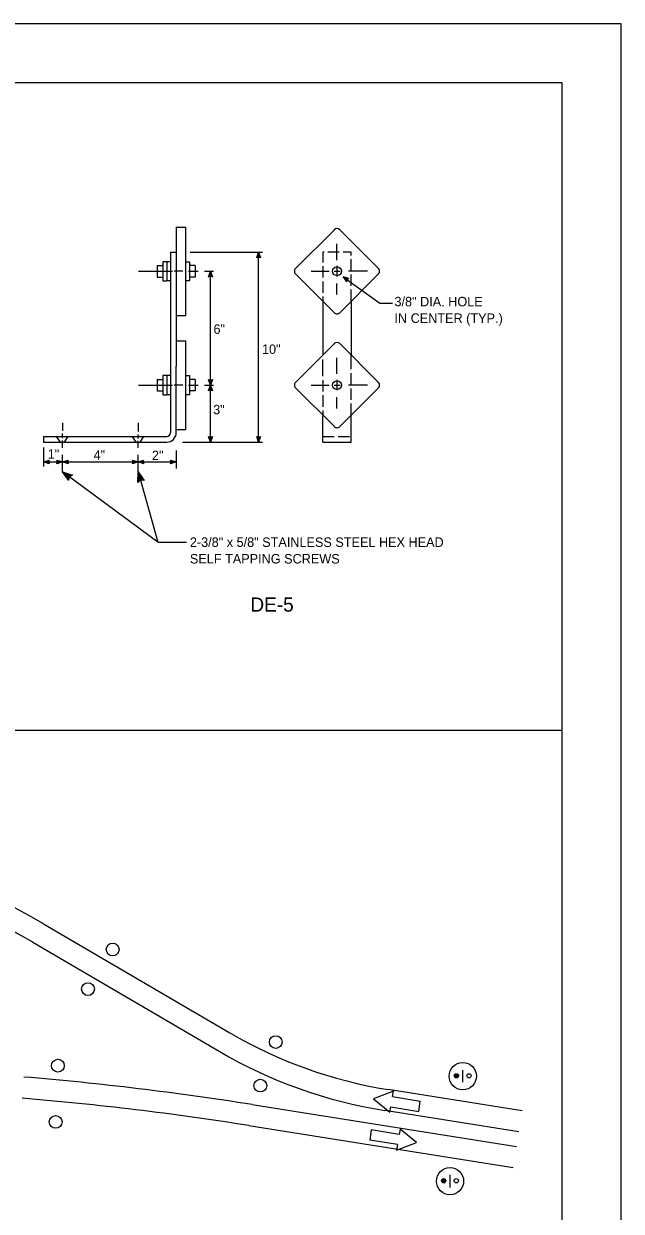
# Model space of a CAD drawing. Extents: x -0.14 to 2.7, y -0.05 to 1.78.
# Drawn here: x 2.172 to 2.698, y 0.736 to 1.781 of the extents above; entities that cross this region are included whole.
import ezdxf

# ---------------------------------------------------------------- set-up
doc = ezdxf.new("R2010")
doc.units = 0
for name, color, linetype in [('BDR_Outer_Perimeter', 7, 'Continuous'), ('BDR_Perimeter', 7, 'Continuous'), ('CT_CSHT_GeneralLabel', 7, 'Continuous')]:
    doc.layers.add(name, color=color, linetype=linetype)

msp = doc.modelspace()

# ---------------------------------------------------------------- linework, layer by layer
at = {"layer": 'BDR_Outer_Perimeter'}
msp.add_lwpolyline([(-0.1354, -0.0521), (2.6979, -0.0521), (2.6979, 1.7812), (-0.1354, 1.7812)], close=True, dxfattribs=at)
at = {"layer": 'BDR_Perimeter'}
for p, q in [((2.6458, 1.7292), (0, 1.7292)), ((2.6458, 0), (2.6458, 1.7292))]:
    msp.add_line(p, q, dxfattribs=at)
at = {"layer": 'CT_CSHT_GeneralLabel'}
for p, q in [((2.3061, 1.6023), (2.3145, 1.6023)), ((2.3061, 1.6023), (2.3061, 1.5801)), ((2.3145, 1.5634), (2.3145, 1.6023)), ((2.4454, 1.5999), (2.4112, 1.5658)), ((2.4843, 1.5658), (2.4501, 1.5999)), ((2.3011, 1.5801), (2.3011, 1.4213)), ((2.3011, 1.5801), (2.3061, 1.5801)), ((2.3061, 1.5801), (2.3061, 1.4798)), ((2.3185, 1.5801), (2.382, 1.5801)), ((2.377, 1.5751), (2.3787, 1.5801)), ((2.3787, 1.5801), (2.3776, 1.5754)), ((2.3787, 1.5801), (2.378, 1.5755)), ((2.3787, 1.5801), (2.3784, 1.5756)), ((2.3787, 1.413), (2.3787, 1.5801)), ((2.3787, 1.5801), (2.3804, 1.5751)), ((2.3787, 1.5801), (2.3787, 1.5756)), ((2.3787, 1.5801), (2.3796, 1.5755)), ((2.3787, 1.5801), (2.3791, 1.5756)), ((2.3787, 1.5801), (2.3799, 1.5753)), ((2.4477, 1.5732), (2.4477, 1.5874)), ((2.2894, 1.5684), (2.2944, 1.5684)), ((2.2894, 1.5684), (2.2894, 1.5583)), ((2.2944, 1.5717), (2.2944, 1.555)), ((2.2978, 1.5717), (2.2944, 1.5717)), ((2.2978, 1.5717), (2.2978, 1.555)), ((2.2978, 1.5717), (2.2978, 1.555)), ((2.3011, 1.5717), (2.2978, 1.5717)), ((2.3145, 1.5717), (2.3178, 1.5717)), ((2.3178, 1.5717), (2.3178, 1.555)), ((2.3229, 1.5684), (2.3178, 1.5684)), ((2.3229, 1.5684), (2.3229, 1.5583)), ((2.4477, 1.5682), (2.4477, 1.5588)), ((2.2729, 1.5634), (2.2965, 1.5634)), ((2.2894, 1.5583), (2.2944, 1.5583)), ((2.2952, 1.5634), (2.303, 1.5634)), ((2.3121, 1.5634), (2.3043, 1.5634)), ((2.3145, 1.5245), (2.3145, 1.5634)), ((2.3171, 1.5634), (2.3254, 1.5634)), ((2.3229, 1.5583), (2.3178, 1.5583)), ((2.3311, 1.5634), (2.3389, 1.5634)), ((2.3346, 1.5583), (2.3363, 1.5634)), ((2.3363, 1.5634), (2.3352, 1.5587)), ((2.3363, 1.5634), (2.3356, 1.5588)), ((2.3363, 1.5634), (2.336, 1.5589)), ((2.3363, 1.5634), (2.338, 1.5583)), ((2.3363, 1.5634), (2.3363, 1.5589)), ((2.3363, 1.5634), (2.3371, 1.5588)), ((2.3363, 1.5634), (2.3367, 1.5589)), ((2.3363, 1.5634), (2.3375, 1.5586)), ((2.3363, 1.4631), (2.3363, 1.5634)), ((2.4112, 1.561), (2.4454, 1.5269)), ((2.425, 1.5634), (2.4407, 1.5634)), ((2.4451, 1.5634), (2.4505, 1.5634)), ((2.4501, 1.5269), (2.4843, 1.561)), ((2.4582, 1.5569), (2.4531, 1.5585)), ((2.4531, 1.5585), (2.4562, 1.5542)), ((2.4531, 1.5585), (2.4567, 1.5559)), ((2.4531, 1.5585), (2.4572, 1.5564)), ((2.4531, 1.5585), (2.4563, 1.5551)), ((2.4531, 1.5585), (2.4576, 1.5567)), ((2.4531, 1.5585), (2.4569, 1.5561)), ((2.4531, 1.5585), (2.4565, 1.5555)), ((2.4531, 1.5585), (2.4562, 1.5547)), ((2.4747, 1.5634), (2.4579, 1.5634)), ((2.2944, 1.555), (2.2978, 1.555)), ((2.3011, 1.555), (2.2978, 1.555)), ((2.3178, 1.555), (2.3145, 1.555)), ((2.4477, 1.5428), (2.4477, 1.5527)), ((2.4352, 1.5371), (2.4352, 1.4898)), ((2.4603, 1.5371), (2.4603, 1.4896)), ((2.3061, 1.5245), (2.3145, 1.5245)), ((2.3061, 1.502), (2.3145, 1.502)), ((2.3145, 1.4631), (2.3145, 1.502)), ((2.4454, 1.4997), (2.4112, 1.4655)), ((2.4843, 1.4655), (2.4501, 1.4997)), ((2.4477, 1.473), (2.4477, 1.4871)), ((2.3061, 1.4213), (2.3061, 1.4798)), ((2.2894, 1.4681), (2.2944, 1.4681)), ((2.2894, 1.4681), (2.2894, 1.4581)), ((2.2944, 1.4715), (2.2944, 1.4547)), ((2.2978, 1.4715), (2.2944, 1.4715)), ((2.2978, 1.4715), (2.2978, 1.4547)), ((2.2978, 1.4715), (2.2978, 1.4547)), ((2.3011, 1.4715), (2.2978, 1.4715)), ((2.3145, 1.4715), (2.3178, 1.4715)), ((2.3178, 1.4715), (2.3178, 1.4547)), ((2.3229, 1.4681), (2.3178, 1.4681)), ((2.3229, 1.4681), (2.3229, 1.4581)), ((2.3363, 1.4631), (2.3346, 1.4681)), ((2.3363, 1.4631), (2.3351, 1.4678)), ((2.3363, 1.4631), (2.3354, 1.4677)), ((2.3363, 1.4631), (2.3359, 1.4676)), ((2.338, 1.4681), (2.3363, 1.4631)), ((2.3363, 1.4631), (2.3374, 1.4678)), ((2.3363, 1.4631), (2.3363, 1.4676)), ((2.3363, 1.4631), (2.337, 1.4676)), ((2.3363, 1.4631), (2.3366, 1.4676)), ((2.4477, 1.4679), (2.4477, 1.4586)), ((2.2729, 1.4631), (2.2965, 1.4631)), ((2.2894, 1.4581), (2.2944, 1.4581)), ((2.2944, 1.4547), (2.2978, 1.4547)), ((2.2952, 1.4631), (2.303, 1.4631)), ((2.3011, 1.4547), (2.2978, 1.4547)), ((2.3121, 1.4631), (2.3043, 1.4631)), ((2.3145, 1.4242), (2.3145, 1.4631)), ((2.3178, 1.4547), (2.3145, 1.4547)), ((2.3171, 1.4631), (2.3254, 1.4631)), ((2.3229, 1.4581), (2.3178, 1.4581)), ((2.3311, 1.4631), (2.3389, 1.4631)), ((2.3346, 1.4581), (2.3363, 1.4631)), ((2.3363, 1.4631), (2.3352, 1.4584)), ((2.3363, 1.4631), (2.3356, 1.4586)), ((2.3363, 1.4631), (2.336, 1.4586)), ((2.3363, 1.413), (2.3363, 1.4631)), ((2.3363, 1.4631), (2.338, 1.4581)), ((2.3363, 1.4631), (2.3363, 1.4586)), ((2.3363, 1.4631), (2.3371, 1.4585)), ((2.3363, 1.4631), (2.3367, 1.4586)), ((2.3363, 1.4631), (2.3375, 1.4584)), ((2.4112, 1.4608), (2.4454, 1.4266)), ((2.425, 1.4631), (2.4407, 1.4631)), ((2.4451, 1.4631), (2.4505, 1.4631)), ((2.4501, 1.4266), (2.4843, 1.4608)), ((2.4747, 1.4631), (2.4579, 1.4631)), ((2.4477, 1.4426), (2.4477, 1.4524)), ((2.4352, 1.413), (2.4352, 1.4362)), ((2.4603, 1.413), (2.4603, 1.4362)), ((2.206, 1.43), (2.206, 1.4229)), ((2.2727, 1.43), (2.2727, 1.4222)), ((2.3061, 1.4242), (2.3145, 1.4242)), ((2.1893, 1.418), (2.1893, 1.413)), ((2.1893, 1.418), (2.2978, 1.418)), ((2.1893, 1.413), (2.2978, 1.413)), ((2.2043, 1.4129), (2.2009, 1.4179)), ((2.206, 1.4163), (2.206, 1.4204)), ((2.206, 1.4078), (2.206, 1.4143)), ((2.2078, 1.4129), (2.2111, 1.4179)), ((2.2709, 1.4129), (2.2676, 1.4179)), ((2.2727, 1.416), (2.2727, 1.4198)), ((2.2727, 1.4078), (2.2727, 1.4142)), ((2.2745, 1.4129), (2.2778, 1.4179)), ((2.3116, 1.413), (2.382, 1.413)), ((2.3363, 1.413), (2.3346, 1.418)), ((2.3363, 1.413), (2.3351, 1.4177)), ((2.3363, 1.413), (2.3354, 1.4176)), ((2.3363, 1.413), (2.3359, 1.4174)), ((2.338, 1.418), (2.3363, 1.413)), ((2.3363, 1.413), (2.3374, 1.4176)), ((2.3363, 1.413), (2.337, 1.4175)), ((2.3363, 1.413), (2.3363, 1.4174)), ((2.3363, 1.413), (2.3366, 1.4174)), ((2.3787, 1.413), (2.3771, 1.418)), ((2.3787, 1.413), (2.3775, 1.4177)), ((2.3787, 1.413), (2.3779, 1.4176)), ((2.3787, 1.413), (2.3783, 1.4174)), ((2.3804, 1.418), (2.3787, 1.413)), ((2.3787, 1.413), (2.3798, 1.4176)), ((2.3787, 1.413), (2.3794, 1.4175)), ((2.3787, 1.413), (2.3787, 1.4174)), ((2.3787, 1.413), (2.3791, 1.4174)), ((2.4352, 1.413), (2.4603, 1.413)), ((2.1893, 1.4082), (2.1893, 1.3914)), ((2.206, 1.3867), (2.206, 1.4017)), ((2.2727, 1.3867), (2.2727, 1.4019)), ((2.3061, 1.4057), (2.3061, 1.3896)), ((2.1894, 1.3955), (2.1944, 1.3971)), ((2.1894, 1.3955), (2.1941, 1.3967)), ((2.1894, 1.3955), (2.194, 1.3963)), ((2.1894, 1.3955), (2.1938, 1.3958)), ((2.1894, 1.3955), (2.2061, 1.3955)), ((2.1944, 1.3938), (2.1894, 1.3955)), ((2.1894, 1.3955), (2.1938, 1.3954)), ((2.1894, 1.3955), (2.1939, 1.3947)), ((2.1894, 1.3955), (2.194, 1.3943)), ((2.1894, 1.3955), (2.1938, 1.3951)), ((2.2011, 1.3971), (2.2061, 1.3955)), ((2.2061, 1.3955), (2.2011, 1.3938)), ((2.2061, 1.3955), (2.2013, 1.3942)), ((2.2061, 1.3955), (2.2014, 1.3966)), ((2.2061, 1.3955), (2.2015, 1.3962)), ((2.2061, 1.3955), (2.2015, 1.3946)), ((2.2061, 1.3955), (2.2016, 1.3958)), ((2.2061, 1.3955), (2.2016, 1.3955)), ((2.2061, 1.3955), (2.2016, 1.3951)), ((2.2061, 1.3955), (2.2111, 1.3971)), ((2.2061, 1.3955), (2.2108, 1.3967)), ((2.2061, 1.3955), (2.2107, 1.3963)), ((2.2061, 1.3955), (2.2105, 1.3958)), ((2.2061, 1.3955), (2.2727, 1.3955)), ((2.2111, 1.3938), (2.2061, 1.3955)), ((2.2061, 1.3955), (2.2105, 1.3954)), ((2.2061, 1.3955), (2.2106, 1.3947)), ((2.2061, 1.3955), (2.2107, 1.3943)), ((2.2061, 1.3955), (2.2105, 1.3951)), ((2.2676, 1.3971), (2.2726, 1.3955)), ((2.2726, 1.3955), (2.2676, 1.3938)), ((2.2726, 1.3955), (2.2679, 1.3966)), ((2.2726, 1.3955), (2.2679, 1.3942)), ((2.2726, 1.3955), (2.268, 1.3946)), ((2.2726, 1.3955), (2.2681, 1.3962)), ((2.2726, 1.3955), (2.2681, 1.3958)), ((2.2726, 1.3955), (2.2681, 1.3951)), ((2.2726, 1.3955), (2.2682, 1.3955)), ((2.2726, 1.3955), (2.2776, 1.3971)), ((2.2726, 1.3955), (2.2774, 1.3967)), ((2.2726, 1.3955), (2.2772, 1.3963)), ((2.2726, 1.3955), (2.2771, 1.3958)), ((2.2776, 1.3938), (2.2726, 1.3955)), ((2.2726, 1.3955), (2.2771, 1.3954)), ((2.2726, 1.3955), (2.2771, 1.3947)), ((2.2726, 1.3955), (2.2773, 1.3943)), ((2.2726, 1.3955), (2.2771, 1.3951)), ((2.2726, 1.3955), (2.306, 1.3955)), ((2.301, 1.3971), (2.306, 1.3955)), ((2.306, 1.3955), (2.301, 1.3938)), ((2.306, 1.3955), (2.3013, 1.3942)), ((2.306, 1.3955), (2.3014, 1.3966)), ((2.306, 1.3955), (2.3014, 1.3946)), ((2.306, 1.3955), (2.3015, 1.3962)), ((2.306, 1.3955), (2.3016, 1.3958)), ((2.306, 1.3955), (2.3016, 1.3955)), ((2.306, 1.3955), (2.3016, 1.3951)), ((2.2115, 1.3793), (2.206, 1.3867)), ((2.206, 1.3867), (2.2148, 1.384)), ((2.206, 1.3867), (2.2123, 1.3822)), ((2.206, 1.3867), (2.2117, 1.3811)), ((2.206, 1.3867), (2.2134, 1.3833)), ((2.206, 1.3867), (2.2115, 1.3804)), ((2.206, 1.3867), (2.212, 1.3817)), ((2.206, 1.3867), (2.2128, 1.3828)), ((2.206, 1.3867), (2.214, 1.3837)), ((2.2723, 1.3775), (2.2727, 1.3867)), ((2.2727, 1.3867), (2.2779, 1.3791)), ((2.2727, 1.3867), (2.2748, 1.3792)), ((2.2727, 1.3867), (2.2737, 1.3788)), ((2.2727, 1.3867), (2.2763, 1.3794)), ((2.2727, 1.3867), (2.2731, 1.3783)), ((2.2727, 1.3867), (2.2743, 1.3791)), ((2.2727, 1.3867), (2.2755, 1.3794)), ((2.2727, 1.3867), (2.277, 1.3794)), ((2.6458, 1.1591), (0, 1.1591)), ((2.1894, 0.9889), (2.3535, 0.8929)), ((2.1799, 0.9728), (2.344, 0.8767)), ((2.5584, 0.8494), (2.5584, 0.8602)), ((2.551, 0.8555), (2.5547, 0.8555)), ((2.551, 0.8545), (2.5546, 0.8545)), ((2.5515, 0.8564), (2.5541, 0.8564)), ((2.5517, 0.8536), (2.554, 0.8536)), ((2.6108, 0.8242), (2.4927, 0.843)), ((2.4965, 0.8368), (2.521, 0.8329)), ((2.6057, 0.7925), (2.373, 0.8297)), ((2.4951, 0.8277), (2.5196, 0.8238)), ((2.5196, 0.8238), (2.521, 0.8329)), ((2.6078, 0.8057), (2.4897, 0.8245)), ((2.6028, 0.7741), (2.37, 0.8112)), ((2.4779, 0.8075), (2.4765, 0.7984)), ((2.5024, 0.8035), (2.4779, 0.8075)), ((2.501, 0.7945), (2.4765, 0.7984)), ((2.5403, 0.764), (2.5429, 0.764)), ((2.5472, 0.7569), (2.5472, 0.7678)), ((2.5398, 0.7631), (2.5434, 0.7631)), ((2.5398, 0.7621), (2.5434, 0.7621)), ((2.5405, 0.7612), (2.5428, 0.7612))]:
    msp.add_line(p, q, dxfattribs=at)
for points in [[(2.4363, 1.5801), (2.4352, 1.5801), (2.4352, 1.5711)], [(2.4496, 1.5801), (2.4396, 1.5801)], [(2.4603, 1.5773), (2.4603, 1.5801), (2.453, 1.5801)], [(2.4603, 1.5639), (2.4603, 1.574)], [(2.4352, 1.5678), (2.4352, 1.5578)], [(2.4531, 1.5585), (2.4853, 1.5352), (2.4965, 1.5352)], [(2.4603, 1.5506), (2.4603, 1.5606)], [(2.4352, 1.5544), (2.4352, 1.5444)], [(2.4603, 1.5372), (2.4603, 1.5472)], [(2.4352, 1.541), (2.4352, 1.5367)], [(2.4352, 1.4709), (2.4352, 1.4857)], [(2.4603, 1.4771), (2.4603, 1.4895)], [(2.4352, 1.4675), (2.4352, 1.4575)], [(2.4603, 1.4637), (2.4603, 1.4737)], [(2.4352, 1.4542), (2.4352, 1.4441)], [(2.4603, 1.4503), (2.4603, 1.4603)], [(2.4603, 1.437), (2.4603, 1.447)], [(2.4352, 1.4408), (2.4352, 1.4364)], [(2.4352, 1.418), (2.4452, 1.418)], [(2.4486, 1.418), (2.4586, 1.418)], [(2.29, 1.3248), (2.206, 1.3867)], [(2.2727, 1.3867), (2.29, 1.3248), (2.3151, 1.3248)], [(2.4965, 0.8368), (2.4973, 0.8416), (2.4797, 0.8349), (2.4943, 0.823), (2.4951, 0.8277)], [(2.501, 0.7945), (2.5002, 0.7896), (2.5178, 0.7963), (2.5032, 0.8082), (2.5024, 0.8035)]]:
    msp.add_lwpolyline(points, dxfattribs=at)
for centre, radius in [((2.4477, 1.5634), 0.00392), ((2.4477, 1.4631), 0.00392), ((2.2502, 0.9663), 0.00563), ((2.2285, 0.9314), 0.00563), ((2.3938, 0.8848), 0.00563), ((2.202, 0.864), 0.00563), ((2.5584, 0.8548), 0.012), ((2.3802, 0.8465), 0.00563), ((2.5528, 0.8551), 0.00187), ((2.5639, 0.8551), 0.00187), ((2.2, 0.8145), 0.00563), ((2.5472, 0.7624), 0.012), ((2.5416, 0.7627), 0.00187), ((2.5527, 0.7627), 0.00187)]:
    msp.add_circle(centre, radius, dxfattribs=at)
for centre, radius, start, end in [((2.4477, 1.5976), 0.00334, 45.0072, 135), ((2.3787, 1.5729), 0.00274, 52.4011, 127.6027), ((2.3363, 1.5562), 0.00274, 52.4011, 127.6027), ((2.4135, 1.5634), 0.00334, 135, 225.0053), ((2.4819, 1.5634), 0.00334, 315, 44.9866), ((2.4589, 1.5543), 0.00274, 106.496, 181.6976), ((2.4477, 1.5292), 0.00334, 224.9898, 314.9932), ((2.4477, 1.4973), 0.00334, 45.0072, 135), ((2.3363, 1.4703), 0.00274, 232.4011, 307.6027), ((2.4135, 1.4631), 0.00334, 135, 225.0053), ((2.4819, 1.4631), 0.00334, 315, 44.9866), ((2.3363, 1.4559), 0.00274, 52.4011, 127.6027), ((2.4477, 1.429), 0.00334, 224.9898, 314.9932), ((2.2978, 1.4213), 0.00835, 270, 360), ((2.2978, 1.4213), 0.00334, 270, 360), ((2.3363, 1.4202), 0.00274, 232.4011, 307.6027), ((2.3787, 1.4202), 0.00274, 232.4011, 307.6027), ((2.1965, 1.3955), 0.00274, 142.3992, 217.6008), ((2.1989, 1.3955), 0.00274, 322.3992, 37.6008), ((2.2133, 1.3955), 0.00274, 142.3992, 217.6008), ((2.2654, 1.3955), 0.00274, 322.3992, 37.6008), ((2.2798, 1.3955), 0.00274, 142.3992, 217.6008), ((2.2989, 1.3955), 0.00274, 322.3992, 37.6008), ((2.2162, 1.3795), 0.00476, 107.028, 182.2297), ((2.2761, 1.3747), 0.00476, 68.2997, 143.5014), ((1.8833, 0.4659), 0.606, 59.6666, 104.0339), ((1.8833, 0.4659), 0.5873, 59.6666, 104.0339), ((2.5558, 1.2386), 0.4006, 239.6659, 260.9326), ((2.5558, 1.2386), 0.4193, 239.6659, 260.9326), ((1.952, -1.8077), 2.6708, 80.9307, 85.276), ((1.952, -1.8077), 2.6521, 80.9307, 85.276)]:
    msp.add_arc(centre, radius, start, end, dxfattribs=at)

# ---------------------------------------------------------------- texts
for s, height, p in [('3/8" DIA. HOLE ', 0.008333, (2.4983, 1.5325)), ('IN CENTER (TYP.)', 0.008333, (2.4983, 1.5179)), ('6"', 0.00833, (2.339, 1.5083)), ('10"', 0.00833, (2.3817, 1.4906)), ('3"', 0.00833, (2.3387, 1.4374)), ('1"', 0.00833, (2.193, 1.3983)), ('4"', 0.00833, (2.2334, 1.3974)), ('2"', 0.00833, (2.2848, 1.3971)), ('2-3/8" x 5/8" STAINLESS STEEL HEX HEAD', 0.008333, (2.3182, 1.3207)), ('SELF TAPPING SCREWS', 0.008333, (2.3182, 1.3061)), ('DE-5', 0.0125, (2.3715, 1.2637))]:
    msp.add_text(s, height=height, dxfattribs=at).set_placement(p)

doc.saveas('drawing.dxf')
